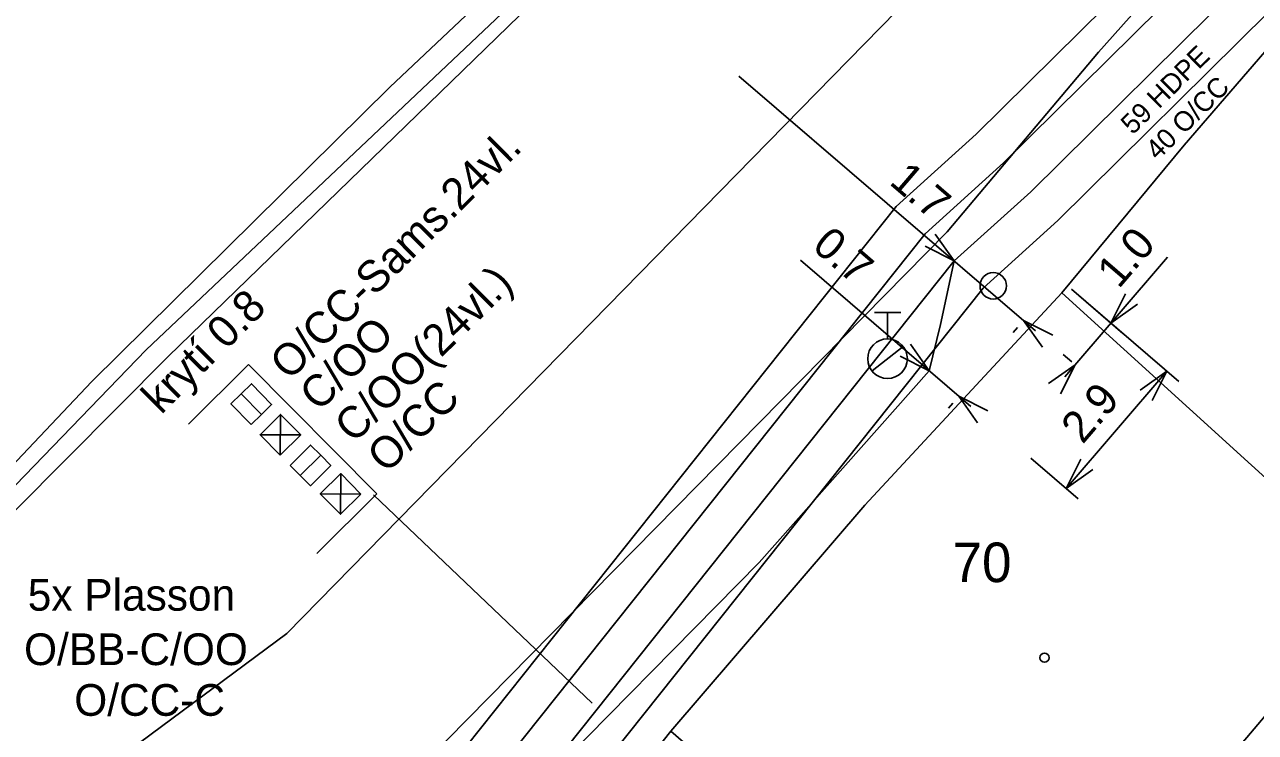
# Model space of a CAD drawing. Extents: x -836739 to -834468, y -1071001 to -1070126.
# Drawn here: x -836503.5 to -836480.21, y -1070304.72 to -1070291.33 of the extents above; entities that cross this region are included whole.
import ezdxf

# ---------------------------------------------------------------- set-up
doc = ezdxf.new("R2010")
doc.units = 0
for name, color, linetype in [('f001_pol_linie', 7, 'Continuous'), ('f001_pol_texty', 7, 'Continuous'), ('f001_pol_znacky', 7, 'Continuous'), ('f003_opt_sit_texty', 7, 'Continuous'), ('f006_osa_trasy', 7, 'Continuous'), ('f006_stp_koty', 7, 'Continuous'), ('f007_rezkynet_linie', 7, 'Continuous'), ('f007_rezkynet_texty', 7, 'Continuous'), ('f007_rezkynet_znacky', 7, 'Continuous'), ('f309_trubka', 7, 'Continuous'), ('f309_trubka_ann', 7, 'Continuous')]:
    doc.layers.add(name, color=color, linetype=linetype)

msp = doc.modelspace()

# ---------------------------------------------------------------- linework, layer by layer
at = {"layer": 'f001_pol_linie'}
for points in [[(-836473.79, -1070281.33), (-836483.18, -1070291.85), (-836486.04, -1070295.25), (-836496.69, -1070306.07), (-836498.64, -1070308.92), (-836508.98, -1070315.34), (-836516.87, -1070318.79), (-836525.05, -1070322.08), (-836528.75, -1070323.23)], [(-836538.28, -1070299.17), (-836536.67, -1070302.12), (-836537.27, -1070302.49), (-836535.82, -1070305.08), (-836535.28, -1070304.8), (-836529.27, -1070315.73), (-836524.75, -1070314.46), (-836523.12, -1070313.78), (-836521.89, -1070313.32), (-836519.48, -1070312.36), (-836516.81, -1070310.51), (-836511.44, -1070307.01), (-836506.56, -1070303.42), (-836500.78, -1070297.61), (-836491.56, -1070288.65), (-836487.98, -1070285.34), (-836486.83, -1070284.4), (-836486.48, -1070284.32), (-836486.34, -1070284.49), (-836485.89, -1070284.09), (-836486.21, -1070283.75)], [(-836521.92, -1070312.95), (-836519.9, -1070312.2), (-836512.67, -1070307.44), (-836507.45, -1070303.71), (-836506.51, -1070302.98), (-836501.2, -1070297.48), (-836487.74, -1070284.74), (-836486.21, -1070283.75)], [(-836486.21, -1070283.75), (-836486.51, -1070283.72), (-836487.17, -1070283.89), (-836488.08, -1070284.48), (-836496.59, -1070292.51), (-836502.23, -1070298.08), (-836506.71, -1070302.82)], [(-836486.39, -1070290.44), (-836498.54, -1070302.85), (-836505.49, -1070308.01), (-836514.78, -1070313.23), (-836530.36, -1070319.04), (-836537.03, -1070321.73), (-836555.38, -1070326.29), (-836561.14, -1070327.96), (-836562.04, -1070328.06)], [(-836481.56, -1070293.61), (-836479.59, -1070291.33)], [(-836483.87, -1070296.4), (-836481.56, -1070293.61)], [(-836487.6, -1070300.42), (-836483.87, -1070296.4), (-836477.87, -1070301.86), (-836484.93, -1070310.21), (-836491.27, -1070304.7)], [(-836487.6, -1070300.42), (-836491.27, -1070304.7)], [(-836491.27, -1070304.7), (-836497.22, -1070312.21), (-836489.89, -1070318.94)]]:
    msp.add_lwpolyline(points, dxfattribs=at)
at = {"layer": 'f001_pol_znacky'}
for p, q in [((-836487.42, -1070296.775), (-836486.92, -1070296.775)), ((-836487.17, -1070297.275), (-836487.17, -1070296.775)), ((-836487.464, -1070297.881), (-836486.874, -1070297.418))]:
    msp.add_line(p, q, dxfattribs=at)
for centre, radius in [((-836485.17, -1070296.27), 0.25), ((-836487.17, -1070297.65), 0.375), ((-836484.2, -1070303.31), 0.0875)]:
    msp.add_circle(centre, radius, dxfattribs=at)
at = {"layer": 'f006_osa_trasy'}
msp.add_lwpolyline([(-836457.65, -1070271.21), (-836461.44, -1070273.73), (-836465.05, -1070276.12), (-836472.49, -1070282.84), (-836476.33, -1070286.14), (-836480.49, -1070290.56), (-836484.46, -1070294.49), (-836485.91, -1070295.8), (-836486.17, -1070297), (-836486.38, -1070297.88), (-836489.6, -1070301.51), (-836494.07, -1070306.05), (-836498.93, -1070309.99), (-836500.26, -1070310.81)], dxfattribs=at)
at = {"layer": 'f006_stp_koty'}
for points in [[(-836484.368, -1070297.123), (-836489.982, -1070292.303)], [(-836486.266, -1070295.294), (-836485.909, -1070295.799), (-836486.461, -1070295.521)], [(-836481.872, -1070295.726), (-836483.817, -1070297.991)], [(-836485.596, -1070298.553), (-836488.817, -1070295.787)], [(-836483.692, -1070296.335), (-836481.656, -1070298.083)], [(-836483.692, -1070296.335), (-836482.718, -1070297.171)], [(-836482.44, -1070296.618), (-836482.945, -1070296.976), (-836482.667, -1070296.423)], [(-836484.71, -1070297.06), (-836484.791, -1070297.155)], [(-836484.238, -1070297.431), (-836484.596, -1070296.927), (-836484.043, -1070297.204)], [(-836486.737, -1070297.375), (-836486.38, -1070297.88), (-836486.932, -1070297.602)], [(-836483.685, -1070297.709), (-836483.849, -1070297.568)], [(-836484.126, -1070298.121), (-836483.622, -1070297.764), (-836483.899, -1070298.316)], [(-836481.884, -1070297.887), (-836483.788, -1070300.105)], [(-836482.388, -1070298.244), (-836481.884, -1070297.887), (-836482.161, -1070298.439)], [(-836485.937, -1070298.489), (-836486.019, -1070298.585)], [(-836485.466, -1070298.861), (-836485.824, -1070298.357), (-836485.271, -1070298.634)], [(-836484.458, -1070299.53), (-836483.561, -1070300.3)], [(-836483.283, -1070299.747), (-836483.788, -1070300.105), (-836483.51, -1070299.552)]]:
    msp.add_lwpolyline(points, dxfattribs=at)
at = {"layer": 'f007_rezkynet_linie'}
msp.add_lwpolyline([(-836492.76, -1070304.17), (-836496.9, -1070300.23)], dxfattribs=at)
at = {"layer": 'f007_rezkynet_znacky'}
for p, q in [((-836499.265, -1070297.762), (-836500.4, -1070298.89)), ((-836496.833, -1070300.208), (-836499.265, -1070297.762)), ((-836498.661, -1070299.475), (-836498.659, -1070298.705)), ((-836498.275, -1070299.091), (-836499.045, -1070299.089)), ((-836497.516, -1070299.825), (-836497.524, -1070300.595)), ((-836497.967, -1070301.336), (-836496.833, -1070300.208)), ((-836497.135, -1070300.214), (-836497.905, -1070300.206))]:
    msp.add_line(p, q, dxfattribs=at)
for points in [[(-836499.019, -1070298.705), (-836498.825, -1070298.514), (-836499.206, -1070298.125), (-836499.4, -1070298.316)], [(-836499.214, -1070298.895), (-836499.019, -1070298.705), (-836499.4, -1070298.316), (-836499.595, -1070298.507)], [(-836498.661, -1070299.475), (-836499.045, -1070299.089), (-836498.659, -1070298.705), (-836498.275, -1070299.091)], [(-836498.475, -1070299.669), (-836498.283, -1070299.862), (-836497.897, -1070299.478), (-836498.089, -1070299.285)], [(-836498.283, -1070299.862), (-836498.091, -1070300.055), (-836497.705, -1070299.671), (-836497.897, -1070299.478)], [(-836497.135, -1070300.214), (-836497.524, -1070300.595), (-836497.905, -1070300.206), (-836497.516, -1070299.825)]]:
    msp.add_lwpolyline(points, close=True, dxfattribs=at)
at = {"layer": 'f309_trubka'}
for points in [[(-836466.468, -1070259.09), (-836459.302, -1070268.728), (-836458.973, -1070269.389), (-836458.634, -1070270.069), (-836462.269, -1070272.48), (-836465.972, -1070274.932), (-836473.482, -1070281.714), (-836477.368, -1070285.054), (-836481.564, -1070289.512), (-836485.491, -1070293.4), (-836487.006, -1070294.77), (-836495.142, -1070304.988), (-836499.8, -1070308.764), (-836506.642, -1070312.996), (-836515.474, -1070317.594), (-836521.802, -1070319.876), (-836532.34, -1070323.572), (-836539.962, -1070325.81), (-836542.393, -1070326.52), (-836543.113, -1070326.73), (-836550.512, -1070328.89)], [(-836458.661, -1070268.334), (-836457.667, -1070270.328), (-836461.855, -1070273.105), (-836465.511, -1070275.526), (-836472.986, -1070282.277), (-836476.849, -1070285.597), (-836481.027, -1070290.036), (-836484.975, -1070293.945), (-836486.458, -1070295.285), (-836494.606, -1070305.519), (-836499.365, -1070309.377), (-836506.271, -1070313.648), (-836515.172, -1070318.282), (-836521.551, -1070320.583), (-836532.11, -1070324.286), (-836539.751, -1070326.53), (-836542.183, -1070327.24), (-836542.903, -1070327.45), (-836550.286, -1070329.605)], [(-836500.259, -1070310.812), (-836498.93, -1070309.99), (-836494.07, -1070306.05), (-836485.91, -1070295.8), (-836484.46, -1070294.49), (-836480.49, -1070290.56), (-836476.33, -1070286.14), (-836472.49, -1070282.84), (-836465.05, -1070276.12), (-836461.44, -1070273.73), (-836458.925, -1070272.058), (-836458.298, -1070271.646), (-836457.635, -1070271.234)], [(-836457.239, -1070271.869), (-836457.883, -1070272.271), (-836458.51, -1070272.683), (-836461.025, -1070274.355), (-836464.589, -1070276.714), (-836471.994, -1070283.403), (-836475.811, -1070286.683), (-836479.953, -1070291.084), (-836483.945, -1070295.035), (-836485.362, -1070296.315), (-836493.534, -1070306.581), (-836498.495, -1070310.603), (-836499.139, -1070311.001)]]:
    msp.add_lwpolyline(points, dxfattribs=at)

# ---------------------------------------------------------------- texts
at = {"layer": 'f001_pol_texty'}
msp.add_text('70', height=0.75, dxfattribs=at).set_placement((-836485.94, -1070301.88))
at = {"layer": 'f003_opt_sit_texty'}
for s, p in [('5x Plasson', (-836503.44, -1070302.42)), ('O/BB-C/OO', (-836503.51, -1070303.45)), ('O/CC-C', (-836502.56, -1070304.41))]:
    msp.add_text(s, height=0.6, dxfattribs=at).set_placement(p)
at = {"layer": 'f006_stp_koty'}
for s, rotation, p in [('1.7', 319.35, (-836487.158, -1070294.331)), ('0.7', 319.35, (-836488.621, -1070295.559)), ('1.0', 49.35, (-836482.797, -1070296.343)), ('2.9', 49.35, (-836483.478, -1070299.284))]:
    msp.add_text(s, height=0.6, rotation=rotation, dxfattribs=at).set_placement(p)
at = {"layer": 'f007_rezkynet_texty'}
for s, rotation, p in [('O/CC-Sams.24vl.', 44.77, (-836498.49, -1070298.08)), ('C/OO(24vl.)', 44.64, (-836497.27, -1070299.27)), ('krytí 0.8', 44.84, (-836500.918, -1070298.723)), ('C/OO', 44.64, (-836497.93, -1070298.67)), ('O/CC', 44.77, (-836496.65, -1070299.84))]:
    msp.add_text(s, height=0.6, rotation=rotation, dxfattribs=at).set_placement(p)
at = {"layer": 'f309_trubka_ann'}
for s, p in [('59 HDPE', (-836482.53, -1070293.424)), ('40 O/CC', (-836482.06, -1070293.909))]:
    msp.add_text(s, height=0.375, rotation=44.7043, dxfattribs=at).set_placement(p)

doc.saveas('drawing.dxf')
